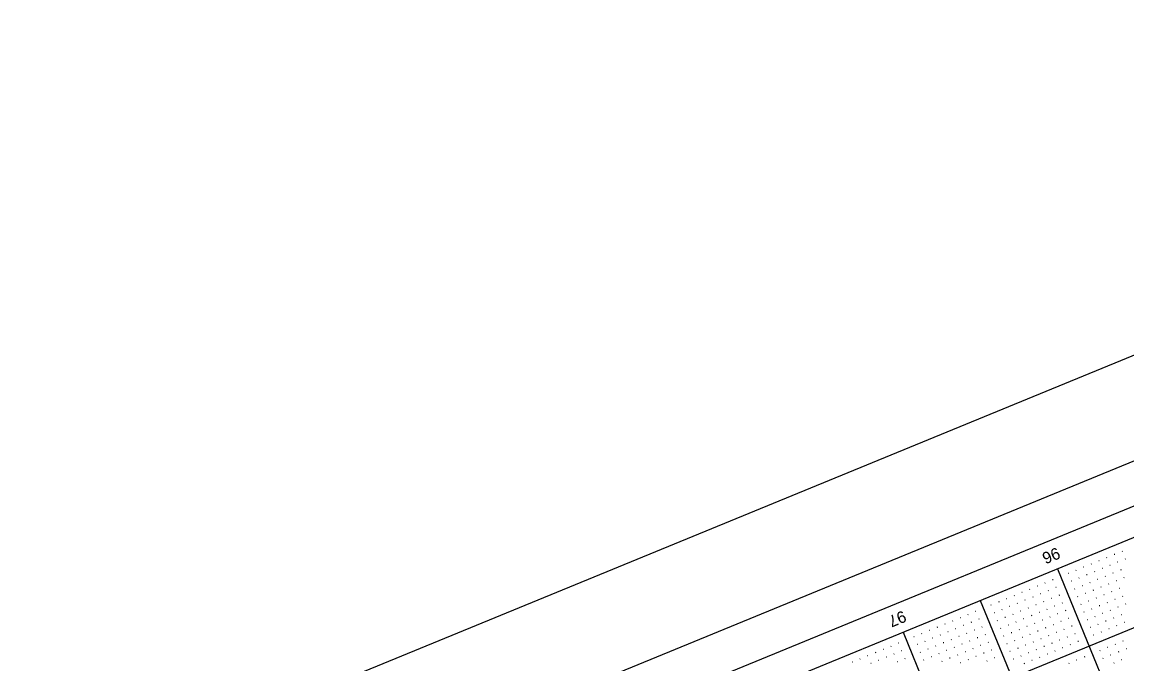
# Model space of a CAD drawing. Extents: x 2148770 to 2150891, y 142633 to 144465.
# Drawn here: x 2149282 to 2149944, y 144042 to 144427 of the extents above; entities that cross this region are included whole.
import ezdxf

# ---------------------------------------------------------------- set-up
doc = ezdxf.new("R2010")
doc.units = 0
for name, color, linetype in [('SHT_Plan_Profile_Sheet_Sta_Txt', 7, 'Continuous'), ('SHT_Plot_Shape_Full', 7, 'Continuous'), ('SHT_Plot_Shape_Half', 7, 'Continuous'), ('SHT_Profile_Grid_Major', 7, 'Continuous'), ('SHT_Profile_Grid_Minor', 7, 'Continuous'), ('SHT_Sheet_Border', 7, 'Continuous')]:
    doc.layers.add(name, color=color, linetype=linetype)

msp = doc.modelspace()

# ---------------------------------------------------------------- linework, layer by layer
at = {"layer": 'SHT_Plot_Shape_Full'}
msp.add_lwpolyline([(2150890.55, 143316.95), (2149225.42, 142633.31), (2148769.66, 143743.39), (2150434.78, 144427.04)], close=True, dxfattribs=at)
at = {"layer": 'SHT_Plot_Shape_Half'}
msp.add_lwpolyline([(2150799.14, 143324.02), (2149226.52, 142678.36), (2148808.74, 143695.93), (2150381.36, 144341.59)], close=True, dxfattribs=at)
at = {"layer": 'SHT_Profile_Grid_Major'}
for p, q in [((2150326.3, 144218.99), (2148869.31, 143620.81)), ((2149902.59, 144099.08), (2150092.49, 143636.55)), ((2149856.33, 144080.09), (2150046.23, 143617.56)), ((2149810.08, 144061.1), (2149999.98, 143598.57))]:
    msp.add_line(p, q, dxfattribs=at)
at = {"layer": 'SHT_Profile_Grid_Minor'}
for p, q in [((2149936.98, 144107.8), (2149936.75, 144107.7)), ((2149941.61, 144109.7), (2149941.37, 144109.6)), ((2149918.48, 144100.2), (2149918.25, 144100.11)), ((2149923.1, 144102.1), (2149922.87, 144102.01)), ((2149927.73, 144104), (2149927.5, 144103.9)), ((2149932.35, 144105.9), (2149932.12, 144105.8)), ((2149934.25, 144101.27), (2149934.02, 144101.18)), ((2149938.88, 144103.17), (2149938.65, 144103.08)), ((2149943.5, 144105.07), (2149943.27, 144104.98)), ((2149909.23, 144096.4), (2149909, 144096.31)), ((2149913.85, 144098.3), (2149913.62, 144098.21)), ((2149915.75, 144093.68), (2149915.52, 144093.58)), ((2149920.38, 144095.58), (2149920.15, 144095.48)), ((2149925, 144097.48), (2149924.77, 144097.38)), ((2149929.63, 144099.37), (2149929.4, 144099.28)), ((2149931.53, 144094.75), (2149931.3, 144094.65)), ((2149936.15, 144096.65), (2149935.92, 144096.55)), ((2149940.78, 144098.55), (2149940.55, 144098.45)), ((2149942.68, 144093.92), (2149942.45, 144093.83)), ((2149886.1, 144086.91), (2149885.87, 144086.81)), ((2149890.73, 144088.81), (2149890.5, 144088.71)), ((2149895.35, 144090.71), (2149895.12, 144090.61)), ((2149899.98, 144092.61), (2149899.75, 144092.51)), ((2149901.88, 144087.98), (2149901.64, 144087.89)), ((2149911.13, 144091.78), (2149910.9, 144091.68)), ((2149913.03, 144087.15), (2149912.79, 144087.06)), ((2149917.65, 144089.05), (2149917.42, 144088.96)), ((2149922.28, 144090.95), (2149922.05, 144090.86)), ((2149924.18, 144086.33), (2149923.94, 144086.23)), ((2149926.9, 144092.85), (2149926.67, 144092.76)), ((2149928.8, 144088.22), (2149928.57, 144088.13)), ((2149933.43, 144090.12), (2149933.19, 144090.03)), ((2149938.05, 144092.02), (2149937.82, 144091.93)), ((2149939.95, 144087.4), (2149939.72, 144087.3)), ((2149872.23, 144081.21), (2149871.99, 144081.12)), ((2149876.85, 144083.11), (2149876.62, 144083.02)), ((2149881.48, 144085.01), (2149881.24, 144084.91)), ((2149883.37, 144080.38), (2149883.14, 144080.29)), ((2149888, 144082.28), (2149887.77, 144082.19)), ((2149892.63, 144084.18), (2149892.39, 144084.09)), ((2149897.25, 144086.08), (2149897.02, 144085.99)), ((2149899.15, 144081.46), (2149898.92, 144081.36)), ((2149903.78, 144083.36), (2149903.54, 144083.26)), ((2149914.92, 144082.53), (2149914.69, 144082.43)), ((2149919.55, 144084.43), (2149919.32, 144084.33)), ((2149921.45, 144079.8), (2149921.22, 144079.71)), ((2149926.07, 144081.7), (2149925.84, 144081.61)), ((2149930.7, 144083.6), (2149930.47, 144083.5)), ((2149935.33, 144085.5), (2149935.09, 144085.4)), ((2149937.22, 144080.87), (2149936.99, 144080.78)), ((2149941.85, 144082.77), (2149941.62, 144082.68)), ((2149853.72, 144073.62), (2149853.49, 144073.52)), ((2149862.97, 144077.41), (2149862.74, 144077.32)), ((2149867.6, 144079.31), (2149867.37, 144079.22)), ((2149869.5, 144074.69), (2149869.27, 144074.59)), ((2149874.12, 144076.59), (2149873.89, 144076.49)), ((2149878.75, 144078.49), (2149878.52, 144078.39)), ((2149880.65, 144073.86), (2149880.42, 144073.77)), ((2149885.27, 144075.76), (2149885.04, 144075.66)), ((2149889.9, 144077.66), (2149889.67, 144077.56)), ((2149894.52, 144079.56), (2149894.29, 144079.46)), ((2149896.42, 144074.93), (2149896.19, 144074.84)), ((2149901.05, 144076.83), (2149900.82, 144076.74)), ((2149905.67, 144078.73), (2149905.44, 144078.63)), ((2149907.57, 144074.1), (2149907.34, 144074.01)), ((2149916.82, 144077.9), (2149916.59, 144077.81)), ((2149918.72, 144073.28), (2149918.49, 144073.18)), ((2149923.35, 144075.18), (2149923.12, 144075.08)), ((2149927.97, 144077.08), (2149927.74, 144076.98)), ((2149932.6, 144078.97), (2149932.37, 144078.88)), ((2149934.5, 144074.35), (2149934.27, 144074.25)), ((2149939.12, 144076.25), (2149938.89, 144076.15)), ((2149943.75, 144078.15), (2149943.52, 144078.05)), ((2149839.85, 144067.92), (2149839.62, 144067.82)), ((2149844.47, 144069.82), (2149844.24, 144069.72)), ((2149849.1, 144071.72), (2149848.87, 144071.62)), ((2149851, 144067.09), (2149850.77, 144067)), ((2149855.62, 144068.99), (2149855.39, 144068.9)), ((2149864.87, 144072.79), (2149864.64, 144072.69)), ((2149866.77, 144068.16), (2149866.54, 144068.07)), ((2149871.4, 144070.06), (2149871.17, 144069.97)), ((2149876.02, 144071.96), (2149875.79, 144071.87)), ((2149877.92, 144067.34), (2149877.69, 144067.24)), ((2149882.55, 144069.23), (2149882.32, 144069.14)), ((2149887.17, 144071.13), (2149886.94, 144071.04)), ((2149889.07, 144066.51), (2149888.84, 144066.41)), ((2149891.8, 144073.03), (2149891.57, 144072.94)), ((2149893.7, 144068.41), (2149893.47, 144068.31)), ((2149898.32, 144070.31), (2149898.09, 144070.21)), ((2149902.95, 144072.21), (2149902.72, 144072.11)), ((2149904.85, 144067.58), (2149904.62, 144067.49)), ((2149909.47, 144069.48), (2149909.24, 144069.38)), ((2149920.62, 144068.65), (2149920.39, 144068.56)), ((2149925.25, 144070.55), (2149925.02, 144070.46)), ((2149929.87, 144072.45), (2149929.64, 144072.35)), ((2149931.77, 144067.82), (2149931.54, 144067.73)), ((2149936.4, 144069.72), (2149936.17, 144069.63)), ((2149941.02, 144071.62), (2149940.79, 144071.53)), ((2149942.92, 144067), (2149942.69, 144066.9)), ((2149821.35, 144060.32), (2149821.12, 144060.23)), ((2149825.97, 144062.22), (2149825.74, 144062.13)), ((2149830.6, 144064.12), (2149830.37, 144064.03)), ((2149835.22, 144066.02), (2149834.99, 144065.92)), ((2149837.12, 144061.39), (2149836.89, 144061.3)), ((2149841.75, 144063.29), (2149841.52, 144063.2)), ((2149846.37, 144065.19), (2149846.14, 144065.1)), ((2149848.27, 144060.57), (2149848.04, 144060.47)), ((2149852.9, 144062.47), (2149852.67, 144062.37)), ((2149857.52, 144064.36), (2149857.29, 144064.27)), ((2149868.67, 144063.54), (2149868.44, 144063.44)), ((2149873.3, 144065.44), (2149873.07, 144065.34)), ((2149875.2, 144060.81), (2149874.96, 144060.72)), ((2149879.82, 144062.71), (2149879.59, 144062.62)), ((2149884.45, 144064.61), (2149884.22, 144064.51)), ((2149886.35, 144059.98), (2149886.11, 144059.89)), ((2149890.97, 144061.88), (2149890.74, 144061.79)), ((2149895.6, 144063.78), (2149895.36, 144063.69)), ((2149900.22, 144065.68), (2149899.99, 144065.59)), ((2149902.12, 144061.06), (2149901.89, 144060.96)), ((2149906.75, 144062.95), (2149906.51, 144062.86)), ((2149911.37, 144064.85), (2149911.14, 144064.76)), ((2149913.27, 144060.23), (2149913.04, 144060.13)), ((2149922.52, 144064.03), (2149922.29, 144063.93)), ((2149927.15, 144065.93), (2149926.91, 144065.83)), ((2149929.05, 144061.3), (2149928.81, 144061.21)), ((2149933.67, 144063.2), (2149933.44, 144063.1)), ((2149938.3, 144065.1), (2149938.06, 144065)), ((2149807.47, 144054.63), (2149807.24, 144054.53)), ((2149816.72, 144058.42), (2149816.49, 144058.33)), ((2149818.62, 144053.8), (2149818.39, 144053.7)), ((2149823.25, 144055.7), (2149823.01, 144055.6)), ((2149827.87, 144057.6), (2149827.64, 144057.5)), ((2149832.5, 144059.5), (2149832.26, 144059.4)), ((2149834.39, 144054.87), (2149834.16, 144054.78)), ((2149839.02, 144056.77), (2149838.79, 144056.67)), ((2149843.65, 144058.67), (2149843.41, 144058.57)), ((2149845.54, 144054.04), (2149845.31, 144053.95)), ((2149850.17, 144055.94), (2149849.94, 144055.85)), ((2149854.8, 144057.84), (2149854.56, 144057.75)), ((2149856.69, 144053.22), (2149856.46, 144053.12)), ((2149859.42, 144059.74), (2149859.19, 144059.64)), ((2149861.32, 144055.11), (2149861.09, 144055.02)), ((2149870.57, 144058.91), (2149870.34, 144058.82)), ((2149872.47, 144054.29), (2149872.24, 144054.19)), ((2149877.09, 144056.19), (2149876.86, 144056.09)), ((2149881.72, 144058.09), (2149881.49, 144057.99)), ((2149883.62, 144053.46), (2149883.39, 144053.36)), ((2149888.24, 144055.36), (2149888.01, 144055.26)), ((2149892.87, 144057.26), (2149892.64, 144057.16)), ((2149897.5, 144059.16), (2149897.26, 144059.06)), ((2149899.39, 144054.53), (2149899.16, 144054.44)), ((2149904.02, 144056.43), (2149903.79, 144056.34)), ((2149908.64, 144058.33), (2149908.41, 144058.23)), ((2149910.54, 144053.7), (2149910.31, 144053.61)), ((2149915.17, 144055.6), (2149914.94, 144055.51)), ((2149924.42, 144059.4), (2149924.19, 144059.31)), ((2149937.47, 144053.95), (2149937.24, 144053.85)), ((2149942.09, 144055.85), (2149941.86, 144055.75)), ((2149788.97, 144047.03), (2149788.74, 144046.93)), ((2149793.59, 144048.93), (2149793.36, 144048.83)), ((2149798.22, 144050.83), (2149797.99, 144050.73)), ((2149802.84, 144052.73), (2149802.61, 144052.63)), ((2149804.74, 144048.1), (2149804.51, 144048.01)), ((2149809.37, 144050), (2149809.14, 144049.91)), ((2149820.52, 144049.17), (2149820.29, 144049.08)), ((2149825.14, 144051.07), (2149824.91, 144050.98)), ((2149829.77, 144052.97), (2149829.54, 144052.88)), ((2149831.67, 144048.35), (2149831.44, 144048.25)), ((2149836.29, 144050.24), (2149836.06, 144050.15)), ((2149840.92, 144052.14), (2149840.69, 144052.05)), ((2149842.82, 144047.52), (2149842.59, 144047.42)), ((2149847.44, 144049.42), (2149847.21, 144049.32)), ((2149852.07, 144051.32), (2149851.84, 144051.22)), ((2149853.97, 144046.69), (2149853.74, 144046.6)), ((2149858.59, 144048.59), (2149858.36, 144048.5)), ((2149863.22, 144050.49), (2149862.99, 144050.39)), ((2149874.37, 144049.66), (2149874.14, 144049.57)), ((2149878.99, 144051.56), (2149878.76, 144051.47)), ((2149880.89, 144046.94), (2149880.66, 144046.84)), ((2149885.52, 144048.83), (2149885.29, 144048.74)), ((2149890.14, 144050.73), (2149889.91, 144050.64)), ((2149894.77, 144052.63), (2149894.54, 144052.54)), ((2149896.67, 144048.01), (2149896.44, 144047.91)), ((2149901.29, 144049.91), (2149901.06, 144049.81)), ((2149905.92, 144051.81), (2149905.69, 144051.71)), ((2149928.22, 144050.15), (2149927.99, 144050.06)), ((2149932.84, 144052.05), (2149932.61, 144051.95)), ((2149934.74, 144047.42), (2149934.51, 144047.33)), ((2149939.37, 144049.32), (2149939.14, 144049.23)), ((2149943.99, 144051.22), (2149943.76, 144051.13)), ((2149779.72, 144043.23), (2149779.49, 144043.14)), ((2149784.34, 144045.13), (2149784.11, 144045.04)), ((2149790.87, 144042.4), (2149790.64, 144042.31)), ((2149795.49, 144044.3), (2149795.26, 144044.21)), ((2149800.12, 144046.2), (2149799.89, 144046.11)), ((2149806.64, 144043.48), (2149806.41, 144043.38)), ((2149811.27, 144045.37), (2149811.04, 144045.28)), ((2149822.42, 144044.55), (2149822.19, 144044.45)), ((2149827.04, 144046.45), (2149826.81, 144046.35)), ((2149833.57, 144043.72), (2149833.34, 144043.63)), ((2149838.19, 144045.62), (2149837.96, 144045.52)), ((2149844.72, 144042.89), (2149844.49, 144042.8)), ((2149849.34, 144044.79), (2149849.11, 144044.7)), ((2149860.49, 144043.96), (2149860.26, 144043.87)), ((2149865.12, 144045.86), (2149864.89, 144045.77)), ((2149876.27, 144045.04), (2149876.04, 144044.94)), ((2149882.79, 144042.31), (2149882.56, 144042.22)), ((2149887.42, 144044.21), (2149887.19, 144044.11)), ((2149892.04, 144046.11), (2149891.81, 144046.01)), ((2149909.72, 144042.55), (2149909.49, 144042.46)), ((2149914.34, 144044.45), (2149914.11, 144044.36)), ((2149918.97, 144046.35), (2149918.74, 144046.26)), ((2149930.12, 144045.52), (2149929.89, 144045.43)), ((2149936.64, 144042.8), (2149936.41, 144042.7)), ((2149941.27, 144044.7), (2149941.04, 144044.6))]:
    msp.add_line(p, q, dxfattribs=at)
at = {"layer": 'SHT_Sheet_Border'}
msp.add_line((2150307.31, 144265.25), (2149093.15, 143766.76), dxfattribs=at)
msp.add_lwpolyline([(2150699.45, 143310.11), (2149242.47, 142711.93), (2148843.68, 143683.25), (2150300.66, 144281.43)], close=True, dxfattribs=at)

# ---------------------------------------------------------------- texts
at = {"layer": 'SHT_Plan_Profile_Sheet_Sta_Txt'}
for s, p in [('96', (2149902.43, 144112.26)), ('97', (2149810.1, 144074.35))]:
    msp.add_text(s, height=7, rotation=202.32131, dxfattribs=at).set_placement(p)

doc.saveas('drawing.dxf')
